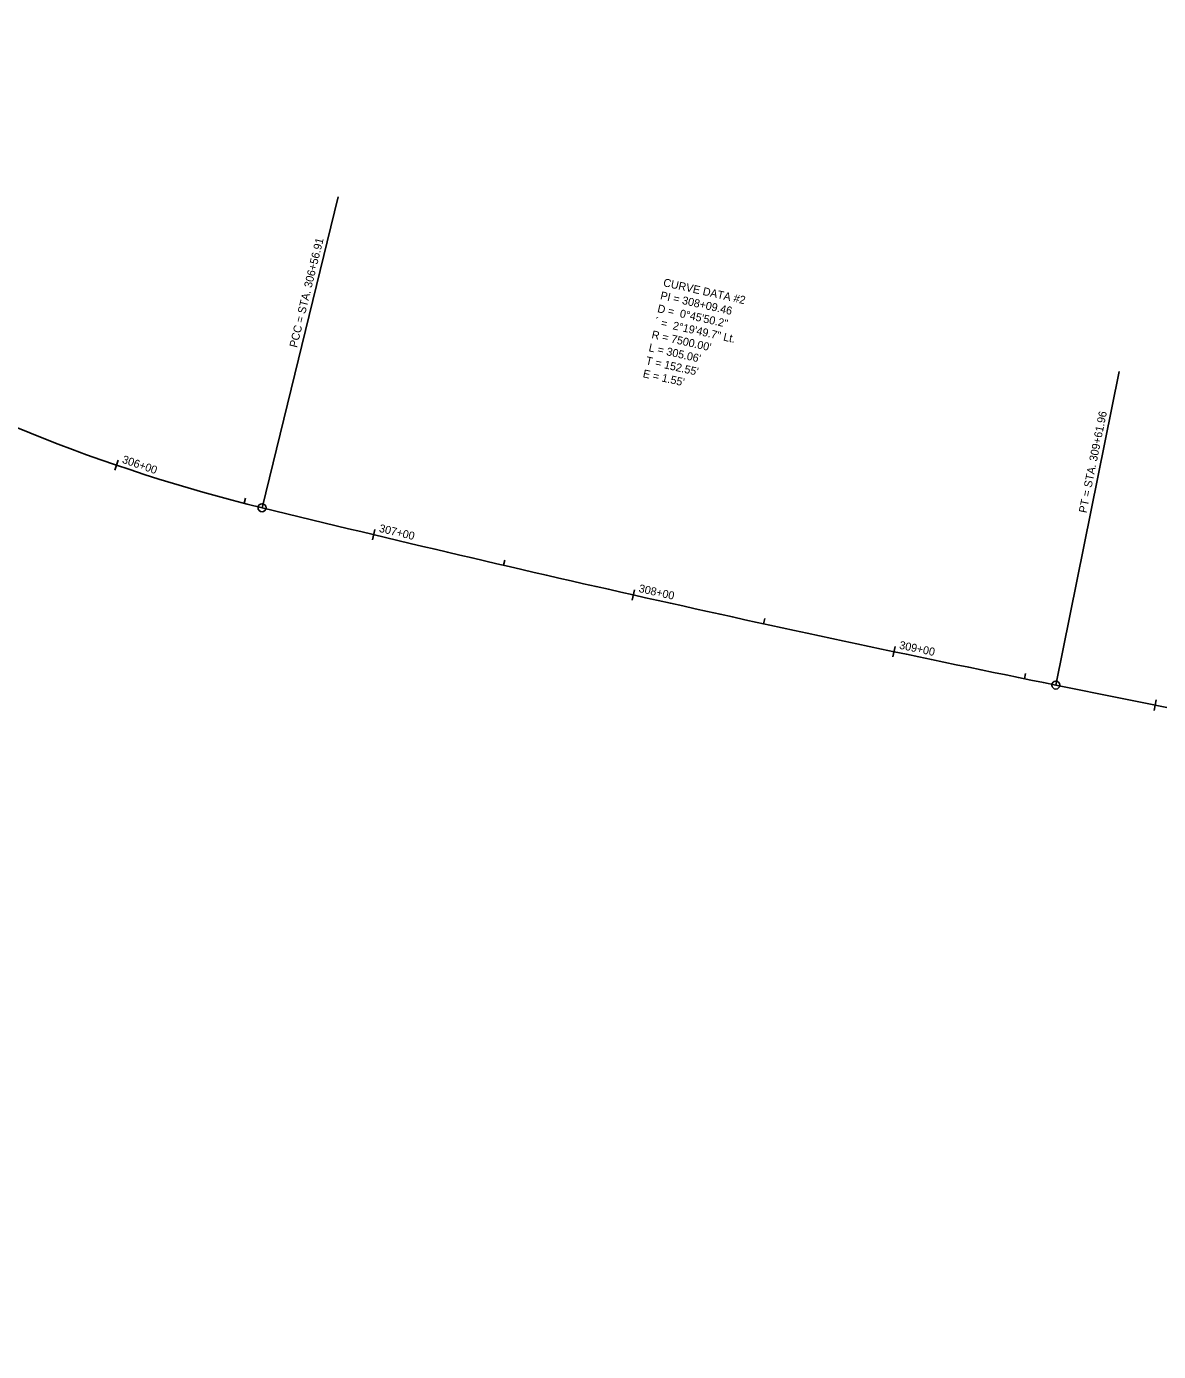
# Model space of a CAD drawing. Extents: x 1158481 to 1165348, y 610053 to 611824.
# Drawn here: x 1158906 to 1159330.5, y 611035.3 to 611532.2 of the extents above; entities that cross this region are included whole.
import ezdxf

# ---------------------------------------------------------------- set-up
doc = ezdxf.new("R2010")
doc.units = 0
for name, color, linetype in [('D_Roadway_Centerline', 7, 'Continuous'), ('D_Roadway_Centerline_CurveData', 7, 'Continuous'), ('D_Roadway_Centerline_Flags', 7, 'Continuous'), ('D_Roadway_Centerline_Text', 7, 'Continuous')]:
    doc.layers.add(name, color=color, linetype=linetype)

msp = doc.modelspace()

# ---------------------------------------------------------------- linework, layer by layer
at = {"layer": 'D_Roadway_Centerline'}
msp.add_line((1159292.01, 611285.23), (1160527.85, 611035.34), dxfattribs=at)
for centre, radius, start, end in [((1159147.28, 611976.3), 643, 223.68131, 256.23809), ((1160778.48, 618636.45), 7500, 256.238085, 258.568558)]:
    msp.add_arc(centre, radius, start, end, dxfattribs=at)
at = {"layer": 'D_Roadway_Centerline_Flags'}
for points in [[(1158994.32, 611351.76), (1159022.87, 611468.31)], [(1159292.01, 611285.23), (1159315.8, 611402.85)]]:
    msp.add_lwpolyline(points, dxfattribs=at)
for centre in [(1158994.32, 611351.76), (1159292.01, 611285.23)]:
    msp.add_circle(centre, 1.5, dxfattribs=at)
at = {"layer": 'D_Roadway_Centerline_Text'}
for points in [[(1158940.36, 611369.61), (1158939.07, 611365.83)], [(1158988.12, 611355.37), (1158987.62, 611353.44)], [(1159036.67, 611343.57), (1159035.74, 611339.68)], [(1159085.33, 611332.12), (1159084.88, 611330.17)], [(1159134.06, 611321), (1159133.18, 611317.09)], [(1159182.87, 611310.2), (1159182.44, 611308.24)], [(1159231.74, 611299.72), (1159230.92, 611295.81)], [(1159280.69, 611289.57), (1159280.29, 611287.61)], [(1159329.69, 611279.66), (1159328.9, 611275.73)]]:
    msp.add_lwpolyline(points, dxfattribs=at)

# ---------------------------------------------------------------- texts
at = {"layer": 'D_Roadway_Centerline_CurveData'}
for s, p in [('CURVE DATA #2', (1159144.58, 611434.89)), ('PI = 308+09.46', (1159143.49, 611430.01)), ('´ =  2%%d19\'49.7" Lt.', (1159141.31, 611420.25)), ('D =  0%%d45\'50.2"', (1159142.4, 611425.13)), ("L = 305.06'", (1159139.13, 611410.49)), ("R = 7500.00'", (1159140.22, 611415.37)), ("T = 152.55'", (1159138.04, 611405.61)), ("E = 1.55'", (1159136.95, 611400.73))]:
    msp.add_text(s, height=3, rotation=347.4033, dxfattribs=at).set_placement(p)
at = {"layer": 'D_Roadway_Centerline_Flags'}
for s, rotation, p in [('PCC = STA. 306+56.91', 76.2381, (1159007.43, 611411.61)), ('PT = STA. 309+61.96', 78.5686, (1159303.5, 611349.6))]:
    msp.add_text(s, height=3, rotation=rotation, dxfattribs=at).set_placement(p)
at = {"layer": 'D_Roadway_Centerline_Text'}
for s, rotation, p in [('306+00', 341.1674, (1158941.62, 611368.66)), ('307+00', 346.5673, (1159038.01, 611342.74)), ('308+00', 347.3312, (1159135.41, 611320.18)), ('309+00', 348.0952, (1159233.11, 611298.92))]:
    msp.add_text(s, height=3, rotation=rotation, dxfattribs=at).set_placement(p)

doc.saveas('drawing.dxf')
